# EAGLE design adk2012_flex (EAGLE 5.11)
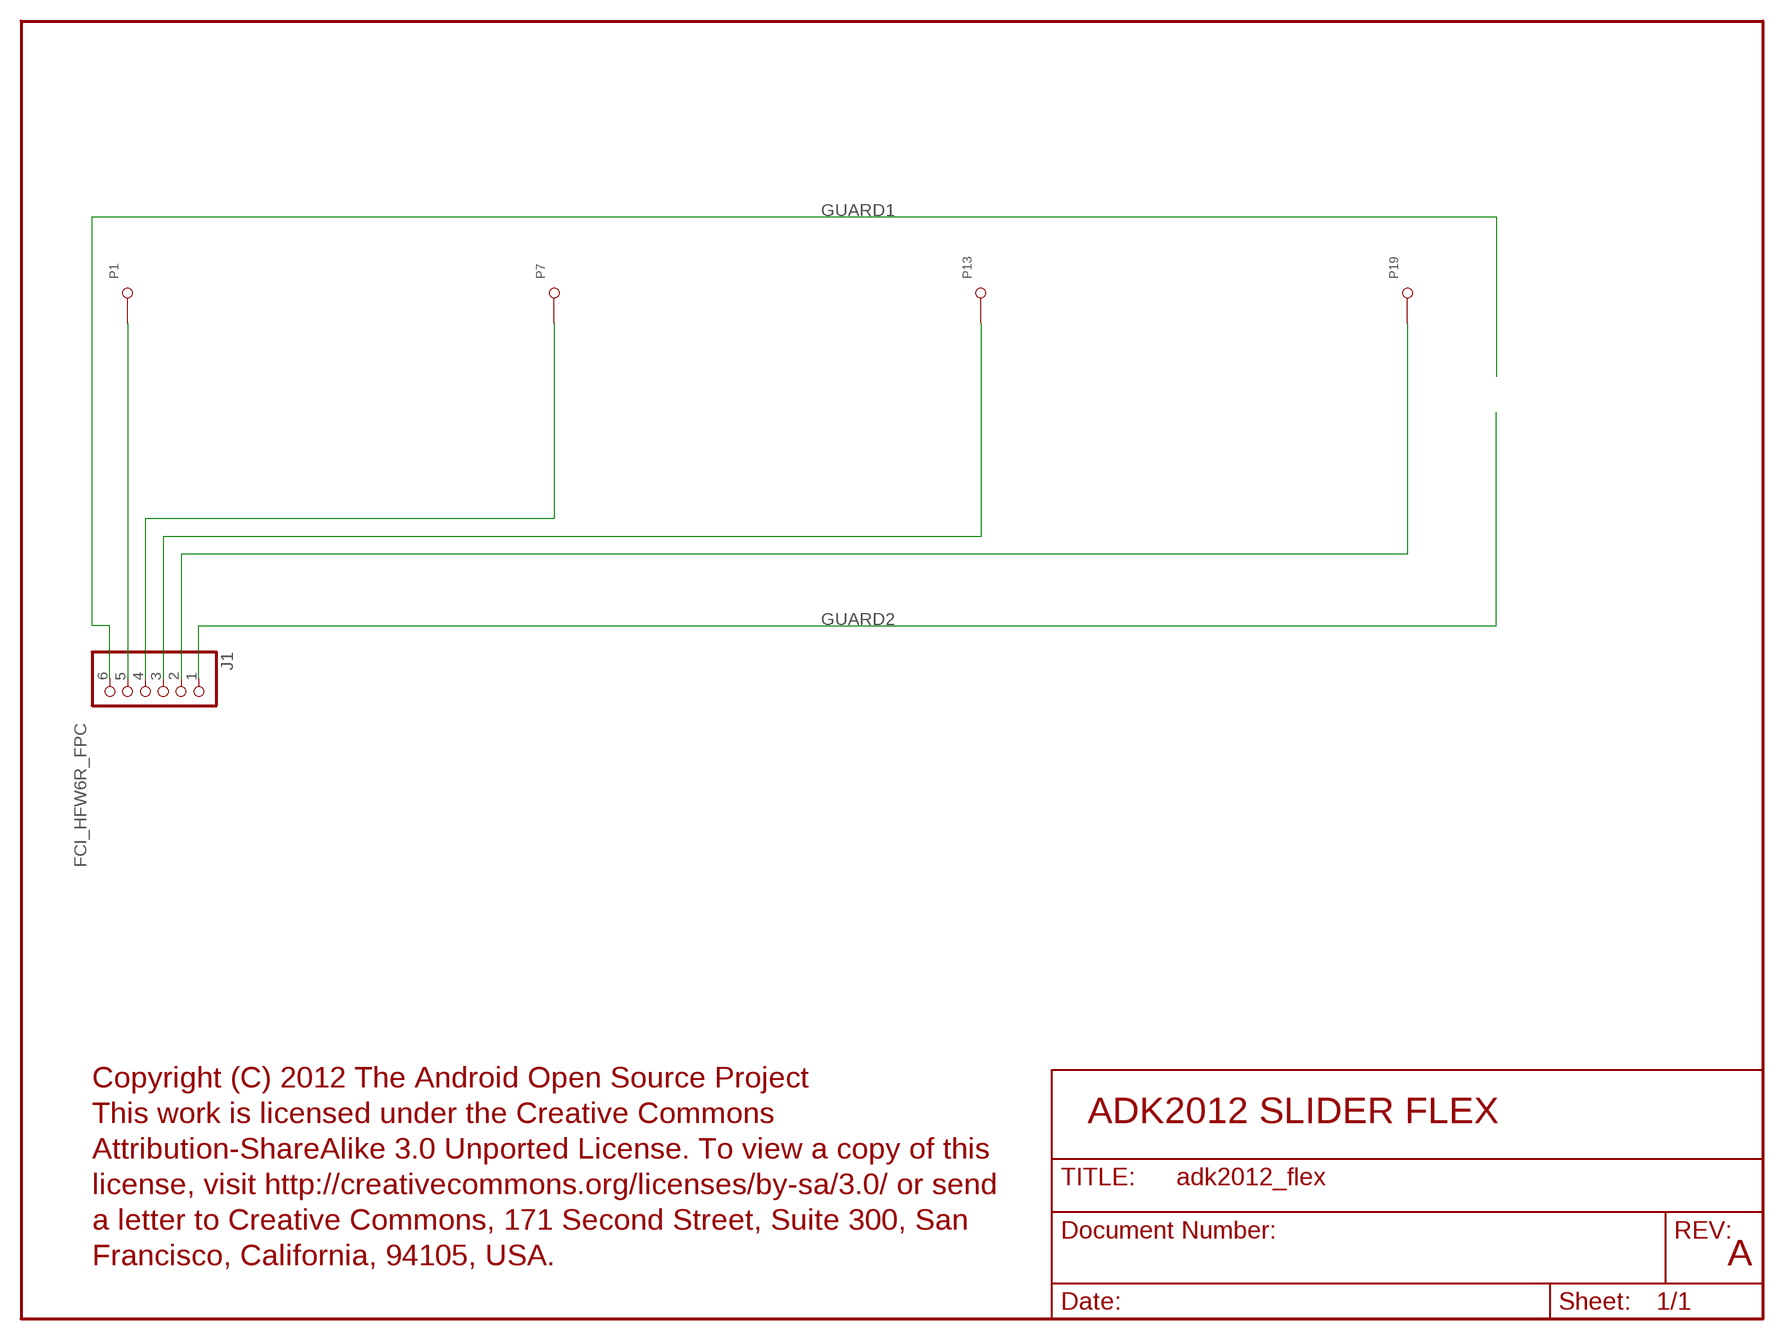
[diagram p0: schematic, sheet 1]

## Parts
J1  FCI_HFW6R_FPC  [FCI_HFW6R_FPC]
P1  CAP_SENSE1  [CAP_SENSE1]
P7  CAP_SENSE1  [CAP_SENSE1]
P13  CAP_SENSE1  [CAP_SENSE1]
P19  CAP_SENSE1  [CAP_SENSE1]

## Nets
GUARD1: J1.6
GUARD2: J1.1
N$6: J1.4 P7.P$1
N$12: J1.3 P13.P$1
N$20: J1.5 P1.P$1
N$21: J1.2 P19.P$1

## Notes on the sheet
- Copyright (C) 2012 The Android Open Source Project
- This work is licensed under the Creative Commons | ADK2012 SLIDER FLEX
- Attribution-ShareAlike 3.0 Unported License. To view a copy of this
- license, visit http://creativecommons.org/licenses/by-sa/3.0/ or send
- a letter to Creative Commons, 171 Second Street, Suite 300, San
- Francisco, California, 94105, USA. | A

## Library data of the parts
J1 = con-misc:FCI_HFW6R_FPC: FCI mating FPC connector layout
P1 P7 P13 P19 = adk2:CAP_SENSE1: Cap sense electrode (NO BOM)

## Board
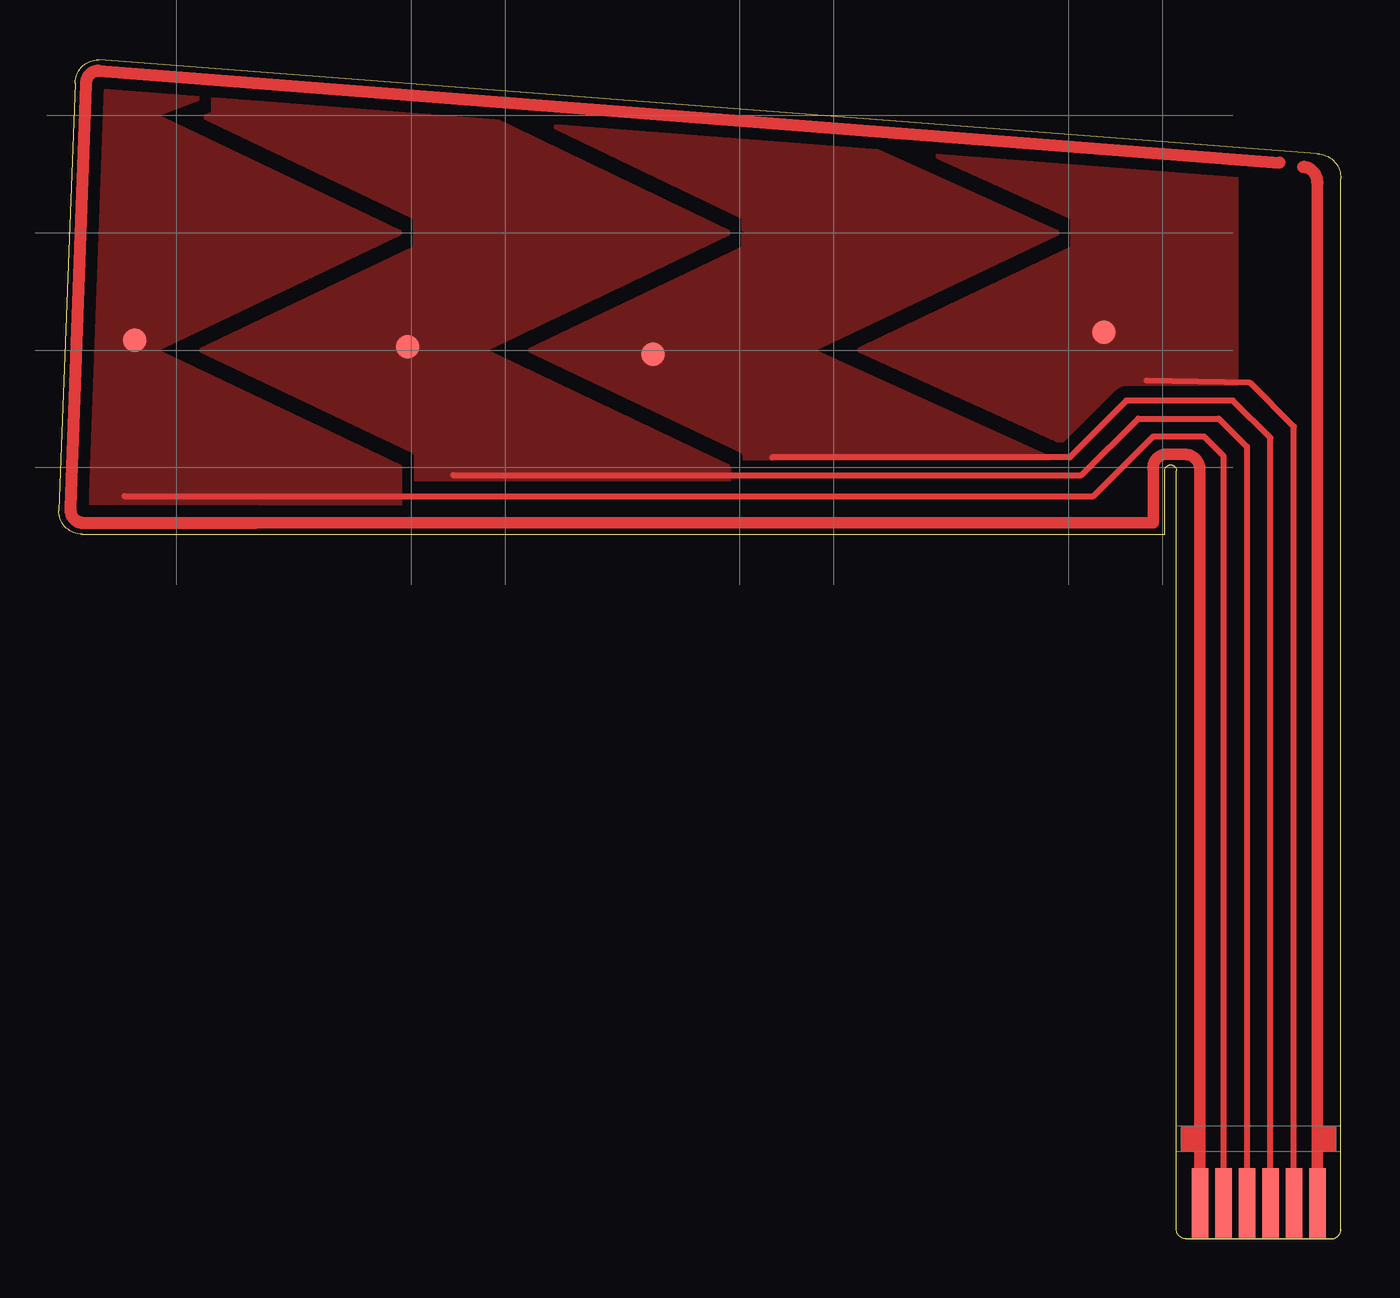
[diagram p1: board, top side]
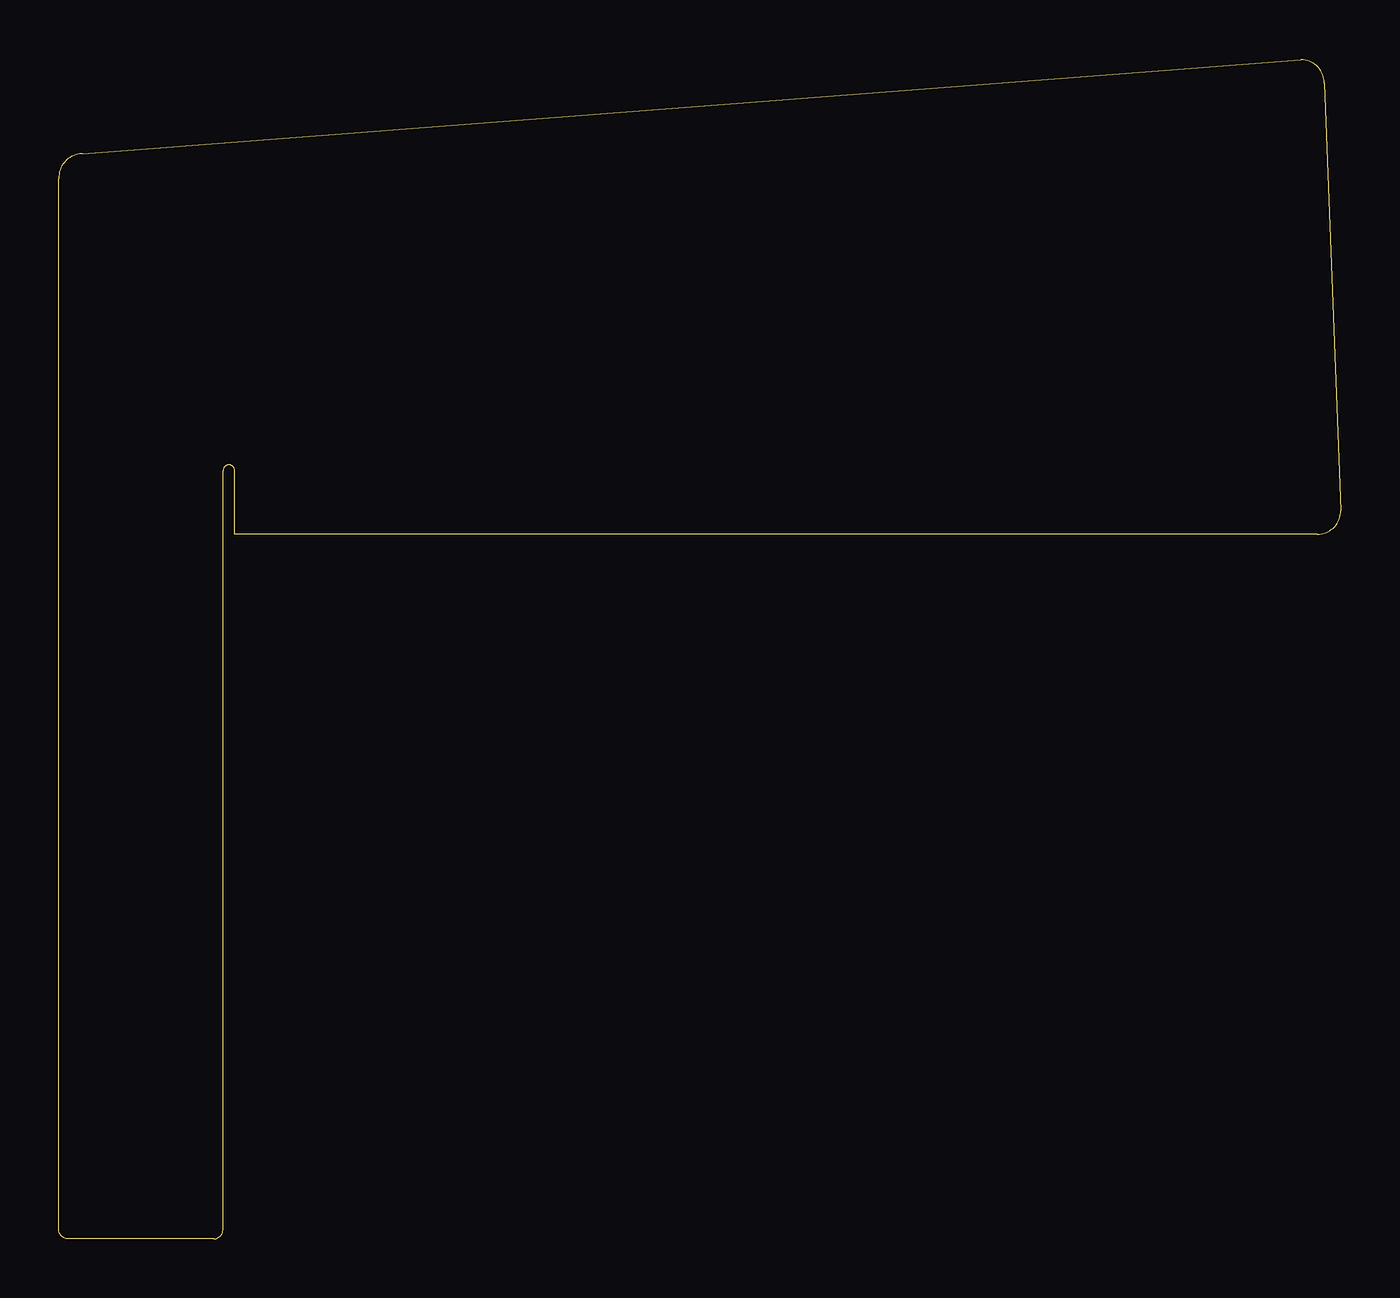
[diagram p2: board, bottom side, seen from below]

Size 54.6 x 50.2 mm. Coordinates in mm from the lower left corner, seen from the top.
Outline: 48,0 arc-90 47.6,0.4 47.6,32.7 arc180 47.1,32.7 47.1,30 1,30 arc-90 0,31 0.7,49.2 arc-90 1.7,50.2 53.6,46.2 arc-90 54.6,45.14 54.6,0.4 arc-90 54.2,0 48,0
Copper layers (1*16): Top 0.035mm / dielectric 1.5mm / Bottom 0.035mm
Design rules "default *": minimum track width 10mil, minimum drill 24mil, track to track 10mil, track to pad 8mil, pad to pad 8mil, via to via 8mil, smd to smd 8mil, copper to edge 40mil, drill to drill 8mil, minimum pad ring 10mil, minimum via ring 8mil, stop-mask expansion 4mil, vias tented up to drill 0mil, thermal gap 10mil

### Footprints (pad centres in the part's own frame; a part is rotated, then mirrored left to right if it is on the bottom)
FCI_HFW6R_FPC = smd 0.7 x 3: 1 -2.5,0; 2 -1.5,0; 3 -0.5,0; 4 0.5,0; 5 1.5,0; 6 2.5,0
CAP_SENSE1 = smd 1 x 1: P$1 0,0

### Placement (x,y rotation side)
J1  51.1,1.5 180 top
P1  3.23,38.25 0 top
P7  14.85,37.97 0 top
P13  25.31,37.66 0 top
P19  44.51,38.59 0 top
U$1  [A3L-LOC]  not placed on the board

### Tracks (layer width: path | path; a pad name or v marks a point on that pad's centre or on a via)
GUARD1
  Top 0.5: 8.38,30.48 46.61,30.48 46.61,32.77 arc-90 47.12,33.4 48.01,33.4 arc-90 48.6,32.68 J1.6
  Top 0.508: 52,45.82 1.7,49.73 arc90 1.17,49.2 1.17,49.15 0.51,31.14 0.51,31.04 arc90 1.02,30.48 8.38,30.48
GUARD2
  Top 0.5: J1.1 53.6,44.94
  Top 0.508: 53.6,44.94 arc90 53,45.64
N$6
  Top 0.254: J1.4 50.6,33.73 49.4,34.92 45.97,34.92 43.56,32.51 16.8,32.51
  pour Top (isolate 0.5, rank 2): 15,30.34 15,32.84 5,37.84 15.5,42.84 5,47.84 8,49.34 17,48.34 28.5,42.84 18,37.84 28.5,32.84 28.5,30.34
N$12
  Top 0.254: J1.3 51.6,34.1 50.01,35.69 45.47,35.69 43.05,33.27 30.38,33.27
  pour Top (isolate 0.5, rank 3): 28.5,30.34 28.5,32.84 19,37.84 29.5,42.84 18.5,48.34 32.5,47.34 42.5,42.84 32,37.84 43,32.84 43,30.34
N$20
  Top 0.254: J1.5 49.6,33.33 48.77,34.16 46.61,34.16 44.07,31.62 2.79,31.62
  pour Top (isolate 0.5): 1.5,49.84 8,49.34 4,47.84 14.5,42.84 4,37.84 14.5,32.84 14.5,30.34 0.5,30.34
N$21
  Top 0.254: J1.2 52.6,34.58 50.75,36.44 46.33,36.54
  pour Top (isolate 0.5, rank 4): 42.5,30.34 42.5,32.84 33,37.84 43,42.84 33,47.34 50.1,45.94 50.1,30.34
(copper drawn outside any net)
  shapes: Top area x2

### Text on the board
Top: Top | 2
Bottom: Bottom | 3
tStop: Overlay Film
Holes: Drills and Milling | 4
Document: Copyright (C) 2012 The Android Open Source Project | This work is licensed under the Creative Commons | Attribution-ShareAlike 3.0 Unported License. To view a copy of this | license, visit http://creativecommons.org/licenses/by-sa/3.0/ or send | a letter to Creative Commons, 171 Second Street, Suite 300, San | Francisco, California, 94105, USA. | ADK2012 Flex | of 4 | ALPHA
Reference: NOTES: | 1. MATERIAL: MAKE FROM POLYIMIDE FILM | WITH 1 OZ. COPPER ON TOP LAYER | 2. PLATING: | A. APPLY SOLDER MASK OVER BARE COPPER (SMOBC) | B. TIN PLATE EXPOSED PADS | C. MINIMUM PLATING THICKNESS 1um | 0.3mm +/- 0.05 | Top Mask Film (Polyimide) | Top Copper (35um INCL. PLATING) | Base Film (25um) | Stiffener (Selective, 76um) | Bottom Adhesive (Selective, 25um) | 0.45mm MAX | Stiffener (Selective, 188um) | Stiffener (76um) | R1, 4pl | 20.2 | 46.2 | 47.6 | 30.0 | Stiffener (188um) | 54.4 | Notes | 1
tDocu: 10 | 4 | 10 | 4 | 10 | 4 | 5 | 5 | 5
FPC_Tape: Supporting Tape
Adhesive: Adhesive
